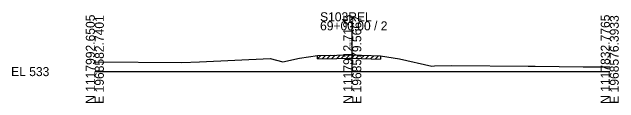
# Model space of a CAD drawing. Extents: x -26 to 163, y -10 to 24518.
# Drawn here: x -25.7 to 162.8, y 17490.3 to 17518.4 of the extents above; entities that cross this region are included whole.
import ezdxf

# ---------------------------------------------------------------- set-up
doc = ezdxf.new("R2010")
doc.units = 0
for name, color, linetype in [('RD_GPK_XS_Cell', 7, 'Continuous'), ('RD_XS_ExGround', 7, 'Continuous'), ('RD_XS_ExPaveRet', 7, 'Continuous'), ('RD_XS_TX_Elev_EX', 7, 'Continuous')]:
    doc.layers.add(name, color=color, linetype=linetype)

msp = doc.modelspace()

# ---------------------------------------------------------------- linework, layer by layer
at = {"layer": 'RD_GPK_XS_Cell'}
for p, q in [((80, 17500), (80, 17515.6)), ((0, 17500), (80, 17500)), ((80, 17500), (160, 17500))]:
    msp.add_line(p, q, dxfattribs=at)
at = {"layer": 'RD_XS_ExGround'}
msp.add_lwpolyline([(0, 17503.06), (27.05, 17502.78), (32.49, 17503), (54.5, 17504.04), (58.45, 17503.02), (63.58, 17504.2), (69.19, 17504.97), (75.2, 17505.11), (78.99, 17505.2), (80, 17505.17), (88.78, 17504.87), (94.7, 17504.01), (104.7, 17501.72), (105.58, 17501.74), (110.91, 17501.86), (134.62, 17501.67), (136.81, 17501.66), (151.72, 17501.51), (160, 17501.44)], dxfattribs=at)
at = {"layer": 'RD_XS_ExPaveRet'}
for p, q in [((69.19, 17503.97), (70.21, 17504.99)), ((69.19, 17503.97), (69.19, 17504.97)), ((69.19, 17503.97), (75.2, 17504.11)), ((70.69, 17504), (71.71, 17505.03)), ((72.19, 17504.04), (73.21, 17505.06)), ((73.69, 17504.07), (74.71, 17505.1)), ((75.19, 17504.11), (76.21, 17505.13)), ((75.2, 17504.11), (78.99, 17504.2)), ((76.69, 17504.14), (77.71, 17505.17)), ((78.19, 17504.18), (79.2, 17505.19)), ((78.99, 17504.2), (80, 17504.17)), ((79.69, 17504.18), (80.66, 17505.14)), ((80, 17504.17), (88.78, 17503.87)), ((81.19, 17504.12), (82.16, 17505.09)), ((82.69, 17504.07), (83.66, 17505.04)), ((84.19, 17504.02), (85.16, 17504.99)), ((85.69, 17503.97), (86.66, 17504.94)), ((87.19, 17503.92), (88.16, 17504.89)), ((88.78, 17504.87), (88.78, 17503.87))]:
    msp.add_line(p, q, dxfattribs=at)

# ---------------------------------------------------------------- texts
at = {"layer": 'RD_GPK_XS_Cell'}
for s, p in [('N 1117992.6505', (0, 17490)), ('E 1968582.7401', (2.8, 17490)), ('N 1117912.7135', (80, 17490)), ('E 1968579.5667', (82.8, 17490)), ('N 1117832.7765', (160, 17490)), ('E 1968576.3933', (162.8, 17490))]:
    msp.add_text(s, height=2.8, rotation=90, dxfattribs=at).set_placement(p)
for s, p in [('S103REL', (70, 17515.6)), ('69+00.00 / 2', (70, 17512.8)), ('EL 533', (-26, 17498.6))]:
    msp.add_text(s, height=2.8, dxfattribs=at).set_placement(p)
at = {"layer": 'RD_XS_TX_Elev_EX'}
msp.add_text('538.17', height=0.8, rotation=90, dxfattribs=at).set_placement((79.9, 17507.17))

doc.saveas('drawing.dxf')
